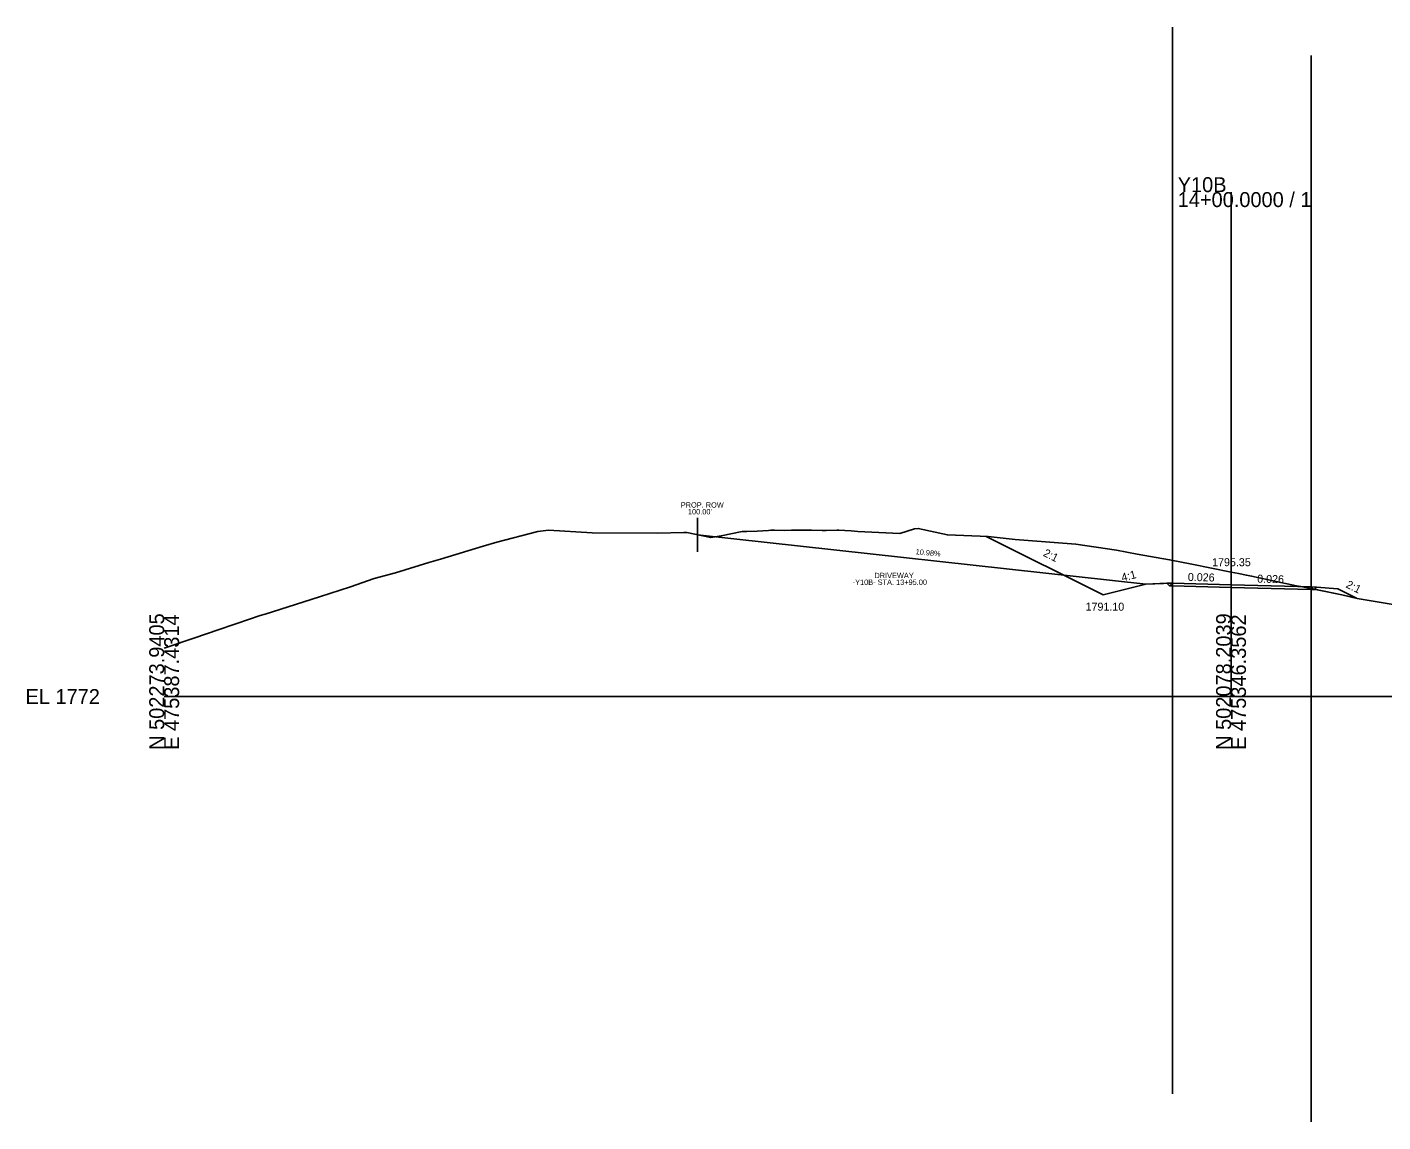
# Model space of a CAD drawing. Extents: x -26 to 1803, y -10 to 9558.
# Drawn here: x -25.7 to 228.5, y 3920.2 to 4125.5 of the extents above; entities that cross this region are included whole.
import ezdxf

# ---------------------------------------------------------------- set-up
doc = ezdxf.new("R2010")
doc.units = 0
for name, color, linetype in [('Exist Cross Section Cell', 7, 'Continuous'), ('Exist XS Center Line Elevation Label', 7, 'Continuous'), ('Exist XS Ground Line', 7, 'Continuous'), ('Pattern 3', 7, 'Continuous'), ('Prop XS Ditch Slope Text', 7, 'Continuous'), ('Prop XS Ditch Standard Text', 7, 'Continuous'), ('Prop XS Dump Level', 7, 'Continuous'), ('Prop XS Earthwork Shape', 7, 'Continuous'), ('Prop XS EOT Tick Mark', 7, 'Continuous'), ('Prop XS Finish Grade', 7, 'Continuous'), ('Prop XS Finish Grade Earthwork', 7, 'Continuous'), ('Prop XS Finish Grade Pavement', 7, 'Continuous'), ('Prop XS Hydro Typical Ditch Data', 7, 'Continuous'), ('Prop XS Pvmt Edge Slope', 7, 'Continuous'), ('Prop XS SE Text', 7, 'Continuous'), ('Prop XS Shoulder Borrow Shape', 7, 'Continuous'), ('Prop XS Side Slope Text', 7, 'Continuous'), ('Prop XS Subgrade Earthwork', 7, 'Continuous'), ('Scratch_Level_2', 7, 'Continuous')]:
    doc.layers.add(name, color=color, linetype=linetype)

msp = doc.modelspace()

# ---------------------------------------------------------------- linework, layer by layer
at = {"layer": 'Exist Cross Section Cell'}
for p, q in [((200, 4000), (200, 4094.59)), ((0, 4000), (200, 4000)), ((200, 4000), (400, 4000))]:
    msp.add_line(p, q, dxfattribs=at)
at = {"layer": 'Exist XS Ground Line'}
msp.add_lwpolyline([(0, 4009.07), (1.12, 4009.47), (8.71, 4012.03), (9.57, 4012.31), (13.65, 4013.68), (18.02, 4015.17), (18.93, 4015.42), (20.33, 4015.86), (29.15, 4018.7), (34.91, 4020.6), (39.37, 4022.11), (43.36, 4023.2), (49.59, 4025.11), (51.81, 4025.77), (59.81, 4028.23), (62.35, 4028.98), (70.03, 4030.93), (72.07, 4031.19), (80.25, 4030.7), (92.46, 4030.61), (97.41, 4030.77), (97.98, 4030.74), (102.47, 4029.82), (104.39, 4030.11), (108.37, 4030.92), (108.93, 4030.96), (109.26, 4030.97), (111.16, 4031.04), (113.28, 4031.15), (113.72, 4031.17), (114.4, 4031.17), (116.27, 4031.15), (117.62, 4031.17), (118.28, 4031.19), (118.65, 4031.2), (119.24, 4031.18), (121.35, 4031.18), (123.38, 4031.15), (124.13, 4031.15), (126.13, 4031.2), (126.45, 4031.2), (127.59, 4031.12), (128.77, 4031.07), (130.04, 4030.92), (137.91, 4030.55), (140.66, 4031.45), (141.36, 4031.53), (146.83, 4030.32), (154.49, 4030.02), (159.54, 4029.47), (170.91, 4028.58), (178.5, 4027.42), (182.42, 4026.72), (188.48, 4025.64), (192.67, 4024.82), (200, 4023.35), (201.41, 4023.07), (202.89, 4022.75), (203.85, 4022.58), (208.46, 4021.6), (212.3, 4020.78), (213.11, 4020.61), (220.75, 4019.09), (223.64, 4018.41), (232.27, 4016.94)], dxfattribs=at)
at = {"layer": 'Pattern 3'}
for p, q in [((100, 4027.12), (100, 4033.54)), ((184, 4021.1), (100, 4030.33)), ((189, 4021.27), (184, 4021.1))]:
    msp.add_line(p, q, dxfattribs=at)
at = {"layer": 'Prop XS Dump Level'}
for p, q in [((189, 4021.27), (200, 4020.98)), ((200, 4020.98), (215, 4020.59))]:
    msp.add_line(p, q, dxfattribs=at)
at = {"layer": 'Prop XS Earthwork Shape'}
for points in [[(176, 4019.1), (154.12, 4030.04), (154.49, 4030.02), (159.54, 4029.47), (170.91, 4028.58), (178.5, 4027.42), (182.42, 4026.72), (188.48, 4025.64), (192.67, 4024.82), (200, 4023.35), (201.41, 4023.07), (202.89, 4022.75), (203.85, 4022.58), (208.46, 4021.6), (212.3, 4020.78), (213.11, 4020.61), (215.63, 4020.11), (215.56, 4020.04), (215, 4020.05), (200, 4020.44), (189, 4020.73), (188.47, 4020.74), (187.98, 4021.24), (184, 4021.1)], [(215.63, 4020.11), (216.03, 4020.51), (220, 4020.19), (223.52, 4018.44), (220.75, 4019.09)]]:
    msp.add_lwpolyline(points, close=True, dxfattribs=at)
at = {"layer": 'Prop XS EOT Tick Mark'}
for p, q in [((189, 4021.27), (189, 4022.27)), ((215, 4020.59), (215, 4021.59))]:
    msp.add_line(p, q, dxfattribs=at)
at = {"layer": 'Prop XS Finish Grade'}
for p, q in [((189, 4021.27), (187.98, 4021.24)), ((215, 4020.59), (216.03, 4020.51))]:
    msp.add_line(p, q, dxfattribs=at)
at = {"layer": 'Prop XS Finish Grade Earthwork'}
for p, q in [((176, 4019.1), (154.12, 4030.04)), ((184, 4021.1), (176, 4019.1)), ((187.98, 4021.24), (184, 4021.1)), ((216.03, 4020.51), (220, 4020.19)), ((223.52, 4018.44), (220, 4020.19))]:
    msp.add_line(p, q, dxfattribs=at)
at = {"layer": 'Prop XS Finish Grade Pavement'}
for p, q in [((189, 4021.27), (200, 4020.98)), ((200, 4020.98), (215, 4020.59))]:
    msp.add_line(p, q, dxfattribs=at)
at = {"layer": 'Prop XS Hydro Typical Ditch Data'}
for p, q in [((176, 4019.1), (154.12, 4030.04)), ((184, 4021.1), (176, 4019.1)), ((223.52, 4018.44), (220, 4020.19))]:
    msp.add_line(p, q, dxfattribs=at)
at = {"layer": 'Prop XS Pvmt Edge Slope'}
for p, q in [((189, 4021.27), (188.47, 4020.74)), ((215, 4020.59), (215.56, 4020.04))]:
    msp.add_line(p, q, dxfattribs=at)
at = {"layer": 'Prop XS Shoulder Borrow Shape'}
for points in [[(189, 4021.27), (187.98, 4021.24), (188.47, 4020.74)], [(215, 4020.59), (216.03, 4020.51), (215.56, 4020.04)]]:
    msp.add_lwpolyline(points, close=True, dxfattribs=at)
at = {"layer": 'Prop XS Subgrade Earthwork'}
for p, q in [((188.47, 4020.74), (187.98, 4021.24)), ((189, 4020.73), (188.47, 4020.74)), ((200, 4020.44), (189, 4020.73)), ((215, 4020.05), (200, 4020.44)), ((215, 4020.05), (215.56, 4020.04)), ((215.56, 4020.04), (216.03, 4020.51))]:
    msp.add_line(p, q, dxfattribs=at)
at = {"layer": 'Scratch_Level_2'}
for p, q in [((189, 4125.53), (189, 3925.53)), ((215, 4120.24), (215, 3920.24))]:
    msp.add_line(p, q, dxfattribs=at)

# ---------------------------------------------------------------- texts
at = {"layer": 'Exist Cross Section Cell'}
for s, p in [('Y10B', (190, 4094.59)), ('14+00.0000 / 1', (190, 4091.79)), ('EL 1772', (-26, 3998.6))]:
    msp.add_text(s, height=2.8, dxfattribs=at).set_placement(p)
for s, p in [('N 502273.9405', (0, 3990)), ('E 475387.4314', (2.8, 3990)), ('N 502078.2039', (200, 3990)), ('E 475346.3562', (202.8, 3990))]:
    msp.add_text(s, height=2.8, rotation=90, dxfattribs=at).set_placement(p)
at = {"layer": 'Exist XS Center Line Elevation Label'}
msp.add_text('1795.35', height=1.5, dxfattribs=at).set_placement((196.45, 4024.44))
at = {"layer": 'Pattern 3'}
for s, p in [('PROP. ROW', (96.85, 4035.43)), ("100.00'", (98.19, 4034.16)), ('-Y10B- STA. 13+95.00', (129.07, 4020.94)), ('DRIVEWAY', (133.15, 4022.2))]:
    msp.add_text(s, height=1, dxfattribs=at).set_placement(p)
msp.add_text('10.98%', height=1, rotation=354.7318, dxfattribs=at).set_placement((140.84, 4026.68))
at = {"layer": 'Prop XS Ditch Slope Text'}
msp.add_text('4:1', height=1.5, rotation=14.0362, dxfattribs=at).set_placement((179.64, 4021.56))
at = {"layer": 'Prop XS Ditch Standard Text'}
msp.add_text('1791.10', height=1.5, dxfattribs=at).set_placement((172.73, 4016.1))
at = {"layer": 'Prop XS Dump Level'}
for p in [(184, 4021.06), (220, 4020.15)]:
    msp.add_text('Case1', height=0.04, dxfattribs=at).set_placement(p)
at = {"layer": 'Prop XS SE Text'}
for p in [(191.89, 4021.69), (204.89, 4021.36)]:
    msp.add_text('0.026', height=1.5, rotation=358.5106, dxfattribs=at).set_placement(p)
at = {"layer": 'Prop XS Side Slope Text'}
for p in [(164.67, 4026.44), (221.41, 4020.53)]:
    msp.add_text('2:1', height=1.5, rotation=333.4349, dxfattribs=at).set_placement(p)

doc.saveas('drawing.dxf')
